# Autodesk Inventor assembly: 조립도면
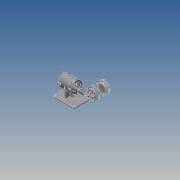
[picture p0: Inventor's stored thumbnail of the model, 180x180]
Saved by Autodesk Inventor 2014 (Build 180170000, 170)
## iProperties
Created: 2015-12
Part Number: 조립도면
Document SubType Name: Assembly
Designer: test_23
Author: test_23
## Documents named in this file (11)
- C:\Users\test_23\Desktop\451207V1035\조립도면.iam
- C:\Users\test_23\Desktop\451207V1035\V-벨트풀리.ipt
- C:\Users\test_23\Desktop\451207V1035\너트 M12x1.25.ipt
- C:\Users\test_23\Desktop\451207V1035\베어링 6204.ipt
- C:\Users\test_23\Desktop\451207V1035\본체.ipt
- C:\Users\test_23\Desktop\451207V1035\볼트 M4 x 12.ipt
- C:\Users\test_23\Desktop\451207V1035\오일실.ipt
- C:\Users\test_23\Desktop\451207V1035\축.ipt
- C:\Users\test_23\Desktop\451207V1035\커버.ipt
- C:\Users\test_23\Desktop\451207V1035\커버2.ipt
- C:\Users\test_23\Desktop\451207V1035\키(4 x 4 x 12).ipt
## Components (5 placed, 5 different names)
1. V-벨트풀리:1
2. KS B 1012 클래스 1 일반 - 미터 M12x1.25:1
3. KS B 2023 6204 - 20 x 47 x 14:1
4. KS B 2804 D D - 20 32 8:1
5. KS B 1311 (I) 4 x 4 x 12:1
